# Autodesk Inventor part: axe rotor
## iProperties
Created: 2011-01
Part Number: axe rotor
Document SubType Name: Modeling
Designer: eric
Density: 1 g/cm^3
Mass: 0.588574 g
Surface Area: 5.08127 cm^2
Volume: 0.588574 cm^3
Author: eric
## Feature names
1. Base1
